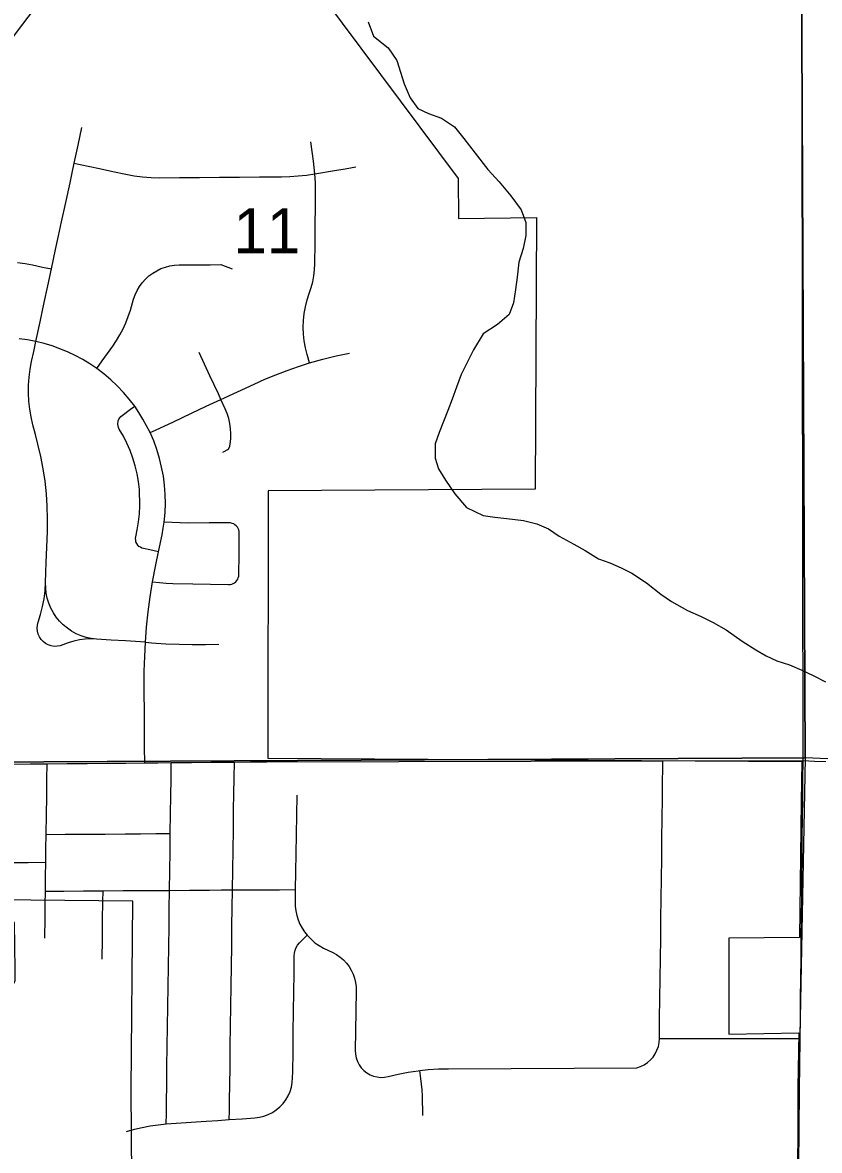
# Model space of a CAD drawing. Extents: x 0 to 34, y 0 to 22.
# Drawn here: x 6.059 to 6.802, y 17.068 to 18.119 of the extents above; entities that cross this region are included whole.
import ezdxf

# ---------------------------------------------------------------- set-up
doc = ezdxf.new("R2010")
doc.units = 0
for name, color, linetype in [('GM_X_City_Street', 7, 'Continuous'), ('GM_X_Corporation', 7, 'Continuous'), ('GM_X_Minor_River', 7, 'Continuous'), ('GM_X_Section_Text', 7, 'Continuous'), ('GM_X_State_Route', 7, 'Continuous'), ('GM_X_Township_Road', 7, 'Continuous')]:
    doc.layers.add(name, color=color, linetype=linetype)

msp = doc.modelspace()

# ---------------------------------------------------------------- linework, layer by layer
at = {"layer": 'GM_X_City_Street'}
for points in [[(6.1739, 17.5416), (6.1553, 17.5428), (6.1418, 17.5437), (6.1282, 17.5446), (6.1234, 17.5452), (6.1186, 17.5462), (6.1139, 17.5477), (6.1094, 17.5496), (6.1051, 17.552), (6.1011, 17.5547), (6.0973, 17.5578), (6.0939, 17.5613), (6.0908, 17.5651), (6.0881, 17.5691), (6.0858, 17.5734), (6.0839, 17.578), (6.0824, 17.5826), (6.0814, 17.5874), (6.0809, 17.5923), (6.0808, 17.5972), (6.0815, 17.6158), (6.082, 17.6303), (6.0825, 17.6449), (6.0827, 17.6566), (6.0824, 17.6683), (6.0816, 17.68), (6.0803, 17.6916), (6.0786, 17.7032), (6.0763, 17.7147), (6.0737, 17.7261), (6.0713, 17.7352), (6.0689, 17.7444), (6.0673, 17.7517), (6.0661, 17.759), (6.0653, 17.7664), (6.0649, 17.7738), (6.065, 17.7813), (6.0655, 17.7887), (6.0664, 17.7961), (6.0678, 17.8034), (6.0698, 17.8126), (6.0718, 17.8219), (6.0757, 17.8401), (6.0796, 17.8584), (6.083, 17.8739), (6.0863, 17.8895), (6.0902, 17.9077), (6.093, 17.9205), (6.0957, 17.9333), (6.0996, 17.9515), (6.1036, 17.9697), (6.1056, 17.979), (6.1075, 17.9882), (6.1111, 18.0048), (6.1147, 18.0213)], [(6.3268, 17.8019), (6.3248, 17.8099), (6.3231, 17.8161), (6.322, 17.8224), (6.3212, 17.8288), (6.321, 17.8352), (6.3212, 17.8416), (6.3219, 17.848), (6.323, 17.8543), (6.3246, 17.8606), (6.3266, 17.8667), (6.3284, 17.8721), (6.3299, 17.8776), (6.3309, 17.8831), (6.3316, 17.8888), (6.3318, 17.8945), (6.332, 17.9131), (6.3321, 17.9317), (6.3323, 17.9467), (6.3324, 17.9617), (6.3323, 17.9699), (6.3318, 17.9781), (6.3313, 17.9841), (6.3305, 17.9901), (6.328, 18.008)], [(6.1075, 17.9882), (6.1129, 17.987), (6.1312, 17.9831), (6.1434, 17.9805), (6.1557, 17.9779), (6.1634, 17.9764), (6.1712, 17.9754), (6.1791, 17.9748), (6.1869, 17.9746), (6.2056, 17.9748), (6.2242, 17.9749), (6.2429, 17.975), (6.2615, 17.9752), (6.2801, 17.9753), (6.2905, 17.9753), (6.3008, 17.9754), (6.3086, 17.9756), (6.3164, 17.9762), (6.3241, 17.977), (6.3318, 17.9781), (6.3502, 17.9812), (6.3602, 17.9829), (6.3702, 17.9846)], [(6.0547, 17.8955), (6.0617, 17.8946), (6.0686, 17.8933), (6.078, 17.8913), (6.0863, 17.8895)], [(6.1285, 17.7968), (6.1336, 17.8038), (6.1434, 17.8176), (6.1469, 17.8228), (6.1501, 17.8282), (6.153, 17.8337), (6.1556, 17.8394), (6.1579, 17.8452), (6.1599, 17.8511), (6.1629, 17.8613), (6.1643, 17.8655), (6.1662, 17.8694), (6.1684, 17.8732), (6.171, 17.8767), (6.1739, 17.88), (6.1772, 17.883), (6.1807, 17.8856), (6.1844, 17.8879), (6.1884, 17.8898), (6.1925, 17.8913), (6.1968, 17.8924), (6.2011, 17.8931), (6.2055, 17.8933), (6.2241, 17.8934), (6.2341, 17.8935), (6.2441, 17.8936), (6.2548, 17.8895)], [(6.1732, 17.4292), (6.1731, 17.4436), (6.173, 17.4622), (6.1729, 17.4808), (6.1728, 17.4911), (6.1727, 17.5014), (6.1728, 17.5148), (6.1732, 17.5282), (6.1739, 17.5416), (6.175, 17.5558), (6.1765, 17.5699), (6.1784, 17.5841), (6.1806, 17.5978), (6.1837, 17.6139), (6.1861, 17.626), (6.1894, 17.6418), (6.1905, 17.6478), (6.1913, 17.6536), (6.1922, 17.6624), (6.1925, 17.6709), (6.1923, 17.6794), (6.1917, 17.6879), (6.1906, 17.6964), (6.189, 17.7048), (6.187, 17.713), (6.1845, 17.7212), (6.1816, 17.7292), (6.1782, 17.737), (6.175, 17.7434), (6.1716, 17.7496), (6.1679, 17.7556), (6.1639, 17.7615), (6.1588, 17.7682), (6.1534, 17.7745), (6.1477, 17.7806), (6.1416, 17.7863), (6.1352, 17.7917), (6.1285, 17.7968), (6.1221, 17.8012), (6.1154, 17.8052), (6.1085, 17.8089), (6.1014, 17.8123), (6.0942, 17.8152), (6.0868, 17.8178), (6.0794, 17.8201), (6.0718, 17.8219), (6.064, 17.8234), (6.0561, 17.8244)], [(6.1782, 17.737), (6.1832, 17.7394), (6.2001, 17.7472), (6.217, 17.7551), (6.2306, 17.7615), (6.2443, 17.7678), (6.2597, 17.775), (6.2752, 17.7822), (6.2853, 17.7868), (6.2956, 17.791), (6.306, 17.795), (6.3165, 17.7986), (6.3268, 17.8019), (6.3394, 17.8054), (6.3518, 17.8085), (6.3643, 17.8111)], [(6.2443, 17.7678), (6.2419, 17.773), (6.234, 17.7899), (6.2289, 17.8007), (6.2239, 17.8116)], [(6.2462, 17.7187), (6.2513, 17.7215), (6.2525, 17.7244), (6.2529, 17.7265), (6.2535, 17.7312), (6.2536, 17.736), (6.2533, 17.7408), (6.2527, 17.7456), (6.2516, 17.7502), (6.2501, 17.7548), (6.2483, 17.7592), (6.2443, 17.7678)], [(6.1861, 17.626), (6.1779, 17.6277), (6.1722, 17.6289), (6.1706, 17.6293), (6.1692, 17.6301), (6.1678, 17.631), (6.1667, 17.6322), (6.1658, 17.6336), (6.1651, 17.6351), (6.1648, 17.6367), (6.1647, 17.6384), (6.1649, 17.64), (6.1662, 17.6465), (6.1675, 17.6539), (6.1683, 17.6614), (6.1688, 17.6689), (6.1683, 17.6839), (6.1674, 17.6913), (6.1661, 17.6987), (6.1644, 17.706), (6.1622, 17.7132), (6.1596, 17.7202), (6.1567, 17.7271), (6.1533, 17.7338), (6.1495, 17.7403), (6.1488, 17.7417), (6.1484, 17.7433), (6.1481, 17.7448), (6.1485, 17.748), (6.1491, 17.7495), (6.1499, 17.7508), (6.1509, 17.7521), (6.1521, 17.7531), (6.16, 17.7588), (6.1639, 17.7615)], [(6.1806, 17.5978), (6.1869, 17.5972), (6.1932, 17.5966), (6.1995, 17.5963), (6.2181, 17.596), (6.2347, 17.5957), (6.2514, 17.5954), (6.2528, 17.5954), (6.2543, 17.5958), (6.2557, 17.5963), (6.257, 17.5971), (6.2581, 17.598), (6.2591, 17.5992), (6.2599, 17.6004), (6.2605, 17.6018), (6.2609, 17.6032), (6.261, 17.6047), (6.2612, 17.6234), (6.2612, 17.6334), (6.2613, 17.6433), (6.2612, 17.6448), (6.2609, 17.6463), (6.2603, 17.6477), (6.2596, 17.649), (6.2586, 17.6501), (6.2574, 17.6511), (6.2562, 17.6519), (6.2548, 17.6524), (6.2533, 17.6528), (6.2518, 17.6529), (6.2332, 17.6528), (6.2137, 17.6526), (6.2063, 17.6528), (6.1988, 17.6532), (6.1913, 17.6536)], [(6.1282, 17.5446), (6.1229, 17.5448), (6.1176, 17.5445), (6.1123, 17.5438), (6.107, 17.5426), (6.1019, 17.5411), (6.097, 17.5391), (6.0943, 17.5382), (6.0887, 17.5377), (6.0859, 17.5382), (6.0833, 17.5391), (6.0808, 17.5404), (6.0786, 17.5422), (6.0766, 17.5442), (6.0751, 17.5466), (6.074, 17.5492), (6.0733, 17.5519), (6.073, 17.5547), (6.0733, 17.5575), (6.074, 17.5603), (6.0762, 17.5675), (6.078, 17.5748), (6.0794, 17.5822), (6.0803, 17.5896), (6.0808, 17.5972)], [(6.1739, 17.5416), (6.1795, 17.5412), (6.1928, 17.5403), (6.2052, 17.5397), (6.2176, 17.5394), (6.23, 17.5396), (6.2424, 17.5399)], [(6.1933, 17.0927), (6.1934, 17.102), (6.1936, 17.1148), (6.1938, 17.1276), (6.194, 17.1462), (6.1943, 17.1649), (6.1946, 17.1835), (6.1948, 17.2021), (6.1951, 17.2208), (6.1954, 17.2394), (6.1956, 17.2581), (6.1959, 17.2767), (6.1961, 17.2936), (6.1964, 17.3104), (6.1966, 17.329), (6.1969, 17.3462), (6.1971, 17.3634), (6.1974, 17.382), (6.1976, 17.3982), (6.1978, 17.4145), (6.198, 17.4295)], [(6.2521, 17.0967), (6.2522, 17.105), (6.2523, 17.1165), (6.2525, 17.128), (6.2528, 17.1467), (6.253, 17.1653), (6.2533, 17.1839), (6.2536, 17.2026), (6.2538, 17.2212), (6.2541, 17.2399), (6.2544, 17.2585), (6.2546, 17.2771), (6.2549, 17.294), (6.2551, 17.3108), (6.2554, 17.3295), (6.2556, 17.3481), (6.2559, 17.3668), (6.2561, 17.3854), (6.2563, 17.4003), (6.2566, 17.4151), (6.2568, 17.43)], [(6.3149, 17.3991), (6.3146, 17.3805), (6.3143, 17.3624), (6.3141, 17.3443), (6.3139, 17.3277), (6.3136, 17.3111), (6.3135, 17.2998), (6.3136, 17.2955), (6.3141, 17.2913), (6.315, 17.2871), (6.3163, 17.283), (6.3179, 17.279), (6.32, 17.2752), (6.3223, 17.2716), (6.3246, 17.2686), (6.3283, 17.2648), (6.3319, 17.2616), (6.3358, 17.2589), (6.34, 17.2566), (6.3485, 17.2524), (6.3521, 17.2505), (6.3554, 17.2482), (6.3584, 17.2455), (6.3612, 17.2426), (6.3637, 17.2394), (6.3658, 17.236), (6.3675, 17.2323), (6.3689, 17.2285), (6.3698, 17.2246), (6.3704, 17.2206), (6.3705, 17.2166), (6.3702, 17.1979), (6.3698, 17.1796), (6.3695, 17.1612), (6.3697, 17.1577), (6.3703, 17.1543), (6.3715, 17.151), (6.3731, 17.1479), (6.3751, 17.145), (6.3775, 17.1425), (6.3803, 17.1404), (6.3833, 17.1386), (6.3865, 17.1373), (6.3899, 17.1365), (6.3934, 17.1361), (6.3969, 17.1363), (6.4003, 17.1369), (6.4095, 17.1391), (6.4188, 17.1409), (6.4281, 17.1423), (6.4297, 17.1425), (6.4376, 17.1433), (6.447, 17.1439), (6.4565, 17.1441), (6.632, 17.145), (6.6355, 17.1462), (6.6388, 17.1478), (6.6419, 17.1499), (6.6447, 17.1523), (6.6471, 17.155), (6.6492, 17.1581), (6.6508, 17.1614), (6.6521, 17.1649), (6.6528, 17.1685), (6.6531, 17.1723), (6.6533, 17.1909), (6.6536, 17.2096), (6.6538, 17.2282), (6.654, 17.2469), (6.6543, 17.2655), (6.6545, 17.2841), (6.6547, 17.3028), (6.655, 17.3214), (6.6552, 17.3401), (6.6554, 17.3587), (6.6557, 17.3773), (6.6559, 17.396), (6.6561, 17.4105), (6.6563, 17.425), (6.6563, 17.431)], [(6.0814, 17.3625), (6.0817, 17.3812), (6.0819, 17.3976), (6.0821, 17.4141), (6.0823, 17.4283)], [(6.081, 17.3366), (6.0812, 17.3495), (6.0814, 17.3625)], [(6.0814, 17.3625), (6.0991, 17.3626), (6.1178, 17.3628), (6.1364, 17.3629), (6.155, 17.3631), (6.1694, 17.3632), (6.1837, 17.3633), (6.1971, 17.3634)], [(5.6669, 17.331), (5.676, 17.3319), (5.6946, 17.3331), (5.7132, 17.3344), (5.7318, 17.3357), (5.7492, 17.3369), (5.7666, 17.3381), (5.7844, 17.3391), (5.8372, 17.3392), (5.8522, 17.3392), (5.9059, 17.3393), (5.9246, 17.3394), (5.9432, 17.3394), (5.9619, 17.3395), (5.9805, 17.3395), (5.9991, 17.3395), (6.0108, 17.3396), (6.0225, 17.3396), (6.035, 17.3362), (6.0498, 17.3363), (6.0647, 17.3364), (6.081, 17.3366)], [(6.08, 17.2658), (6.0803, 17.2844), (6.0805, 17.297), (6.0806, 17.3095), (6.0808, 17.323), (6.081, 17.3366)], [(6.0806, 17.3095), (6.0977, 17.3097), (6.1161, 17.3098), (6.1344, 17.3099), (6.1531, 17.3101), (6.1717, 17.3102), (6.184, 17.3103), (6.1964, 17.3104), (6.215, 17.3105), (6.2337, 17.3107), (6.2444, 17.3108), (6.2551, 17.3108), (6.2696, 17.3109), (6.2842, 17.311), (6.2989, 17.311), (6.3136, 17.3111)], [(6.1335, 17.2464), (6.1338, 17.2651), (6.134, 17.2825), (6.1343, 17.3), (6.1344, 17.3099)], [(6.1564, 17.0856), (6.1636, 17.0877), (6.1709, 17.0895), (6.1783, 17.091), (6.1858, 17.092), (6.1933, 17.0927), (6.2119, 17.094), (6.2305, 17.0953), (6.2413, 17.096), (6.2521, 17.0967), (6.264, 17.0975), (6.2758, 17.0983), (6.2801, 17.0989), (6.2843, 17.0999), (6.2884, 17.1014), (6.2923, 17.1034), (6.2959, 17.1058), (6.2992, 17.1086), (6.3022, 17.1117), (6.3048, 17.1152), (6.307, 17.1189), (6.3087, 17.1229), (6.31, 17.127), (6.3108, 17.1313), (6.3111, 17.1356), (6.3112, 17.1412), (6.3115, 17.1599), (6.3117, 17.1785), (6.312, 17.1972), (6.3123, 17.2158), (6.3125, 17.2325), (6.3127, 17.2493), (6.313, 17.2519), (6.3136, 17.2545), (6.3145, 17.257), (6.3158, 17.2593), (6.3174, 17.2614), (6.3193, 17.2633), (6.3246, 17.2686)], [(6.6531, 17.1723), (6.7036, 17.1723), (6.7843, 17.1723)], [(6.4325, 17.1006), (6.4323, 17.119), (6.4318, 17.1246), (6.4306, 17.135), (6.4297, 17.1425)]]:
    msp.add_lwpolyline(points, dxfattribs=at)
at = {"layer": 'GM_X_Corporation'}
for points in [[(5.7966, 18.4409), (6.7843, 18.4413), (6.7891, 17.4339), (5.7831, 17.4286)], [(7.7907, 18.396), (7.7756, 17.4406), (7.775, 17.3902), (6.7891, 17.4339), (6.7843, 18.4413)], [(5.7831, 17.4286), (6.7891, 17.4339), (6.7694, 16.4145), (5.7675, 16.4186)]]:
    msp.add_lwpolyline(points, close=True, dxfattribs=at)
for points in [[(6.3391, 18.1436), (6.4654, 17.9737), (6.4659, 17.9367), (6.5384, 17.9375), (6.5373, 17.6843), (6.2884, 17.6827), (6.288, 17.4335), (6.7859, 17.4306), (6.7851, 17.3933), (6.7838, 17.2666), (6.7178, 17.2657), (6.7179, 17.1763), (6.7829, 17.1775), (6.7822, 17.1268), (6.7822, 17.048)], [(6.1613, 17.0421), (6.1606, 17.1246), (6.1621, 17.3004), (6.0352, 17.3017), (6.0514, 17.2802), (6.0523, 17.2367), (6.0522, 17.2257), (6.0381, 17.1992), (6.0253, 17.1777), (6.0066, 17.1509), (6.0071, 17.069), (5.9443, 17.0712), (5.9443, 17.0913), (5.9074, 17.0906), (5.9044, 16.9491)]]:
    msp.add_lwpolyline(points, dxfattribs=at)
at = {"layer": 'GM_X_Minor_River'}
for points in [[(6.3816, 18.12), (6.3865, 18.1065), (6.4003, 18.0955), (6.4083, 18.0839), (6.415, 18.0621), (6.4207, 18.049), (6.4277, 18.039), (6.4378, 18.0345), (6.4498, 18.03), (6.4621, 18.0221), (6.4706, 18.0112), (6.4812, 17.9973), (6.493, 17.9821), (6.5037, 17.9708), (6.5147, 17.9576), (6.5242, 17.9445), (6.5285, 17.9329), (6.5286, 17.9208), (6.526, 17.9087), (6.5219, 17.8959), (6.5204, 17.8818)], [(6.5204, 17.8818), (6.5189, 17.8705), (6.5171, 17.858), (6.513, 17.8471), (6.5022, 17.8378), (6.4887, 17.8291), (6.4799, 17.8141), (6.4735, 17.8017), (6.4683, 17.7912), (6.4639, 17.7795), (6.4598, 17.7682), (6.4557, 17.7577), (6.4517, 17.7475), (6.4476, 17.737), (6.4439, 17.7265), (6.444, 17.7132), (6.4471, 17.7032), (6.4537, 17.6927), (6.4625, 17.68), (6.4731, 17.6671), (6.4889, 17.6599), (6.4995, 17.6581), (6.5108, 17.657), (6.5263, 17.6551), (6.5388, 17.6521), (6.5496, 17.6473), (6.5597, 17.6406), (6.5732, 17.633), (6.584, 17.627), (6.5964, 17.6194), (6.6069, 17.6157), (6.6174, 17.6109), (6.6275, 17.6061), (6.6409, 17.597), (6.6543, 17.5864), (6.6644, 17.5796), (6.6793, 17.5713), (6.6921, 17.5656), (6.7033, 17.56), (6.7153, 17.5532), (6.7302, 17.5426), (6.7429, 17.5346), (6.7526, 17.5291), (6.7624, 17.5242), (6.7744, 17.5205), (6.786, 17.5156), (6.7969, 17.5104), (6.8078, 17.5048)]]:
    msp.add_lwpolyline(points, dxfattribs=at)
at = {"layer": 'GM_X_State_Route'}
for points in [[(5.947, 17.427), (5.9656, 17.4272), (5.9801, 17.4273), (5.9946, 17.4275), (6.0133, 17.4277), (6.0319, 17.4278), (6.0506, 17.428), (6.0664, 17.4282), (6.0823, 17.4283), (6.101, 17.4285), (6.1196, 17.4287), (6.1382, 17.4289), (6.1557, 17.429), (6.1732, 17.4292), (6.1856, 17.4293), (6.198, 17.4295), (6.2167, 17.4296), (6.2353, 17.4298), (6.2461, 17.4299), (6.2568, 17.43), (6.2718, 17.4302), (6.2871, 17.4303), (6.6563, 17.431), (6.7871, 17.4313)], [(6.7871, 17.4313), (6.7976, 17.4309), (6.8081, 17.4305)]]:
    msp.add_lwpolyline(points, dxfattribs=at)
at = {"layer": 'GM_X_Township_Road'}
for points in [[(6.7871, 17.4313), (6.7856, 18.4436)], [(5.8743, 17.8254), (5.8774, 17.8425), (5.8799, 17.8549), (5.8823, 17.865), (5.8835, 17.8695), (5.8874, 17.8831), (5.8944, 17.8955), (5.9044, 17.909), (5.9144, 17.9226), (5.9255, 17.9375), (5.9367, 17.9525), (5.9478, 17.9675), (5.9589, 17.9825), (5.97, 17.9974), (5.9811, 18.0124), (5.9922, 18.0274), (6.0033, 18.0423), (6.0145, 18.0573), (6.0256, 18.0723), (6.0321, 18.0811), (6.0387, 18.0899), (6.0499, 18.1048), (6.0597, 18.1178), (6.0694, 18.1308)], [(6.7853, 17.266), (6.7855, 17.2847), (6.7857, 17.3033), (6.7859, 17.3219), (6.7861, 17.3406), (6.7863, 17.3592), (6.7865, 17.3779), (6.7867, 17.3965), (6.7869, 17.4139), (6.7871, 17.4313)], [(6.7843, 17.1723), (6.7845, 17.191), (6.7847, 17.2096), (6.7849, 17.2283), (6.7851, 17.2469), (6.7852, 17.2565), (6.7853, 17.266)], [(6.783, 17.0504), (6.7831, 17.0618), (6.7833, 17.0804), (6.7835, 17.0991), (6.7836, 17.1128), (6.7838, 17.1265), (6.784, 17.1452), (6.7841, 17.1549), (6.7842, 17.1646), (6.7843, 17.1723)]]:
    msp.add_lwpolyline(points, dxfattribs=at)

# ---------------------------------------------------------------- texts
at = {"layer": 'GM_X_Section_Text'}
msp.add_text('11', height=0.04186, rotation=0, dxfattribs=at).set_placement((6.256, 17.9042))

doc.saveas('drawing.dxf')
